Omron CX-Programmer project NuevoProyecto (CX-Programmer 9.50)

# PLC NewPLC1: CP1L-E EM

## Program P17_1_2 (cyclic task 0)
Local symbols
EV1 100.01 BOOL
EV2 100.02 BOOL
EV3 100.03 BOOL
Etapa_0 10.00 BOOL
Etapa_1 10.01 BOOL
Etapa_10 10.10 BOOL
Etapa_11 10.11 BOOL
Etapa_12 10.12 BOOL
Etapa_2 10.02 BOOL
Etapa_3 10.03 BOOL
Etapa_4 10.04 BOOL
Etapa_5 10.05 BOOL
Etapa_6 10.06 BOOL
Etapa_7 10.07 BOOL
Etapa_8 10.08 BOOL
Etapa_9 10.09 BOOL
F1 0.02 BOOL
FSF1 15.00 BOOL  ; Flanco Subida F1
MC 100.00 BOOL
S_1 0.01 BOOL
X 15.01 BOOL  ; Auxiliar X
Y 15.02 BOOL  ; Auxiliar Y
m 0.00 BOOL

### Section Sección1_Programa_principal
; Programa principal (Etapas 0 ... 23)

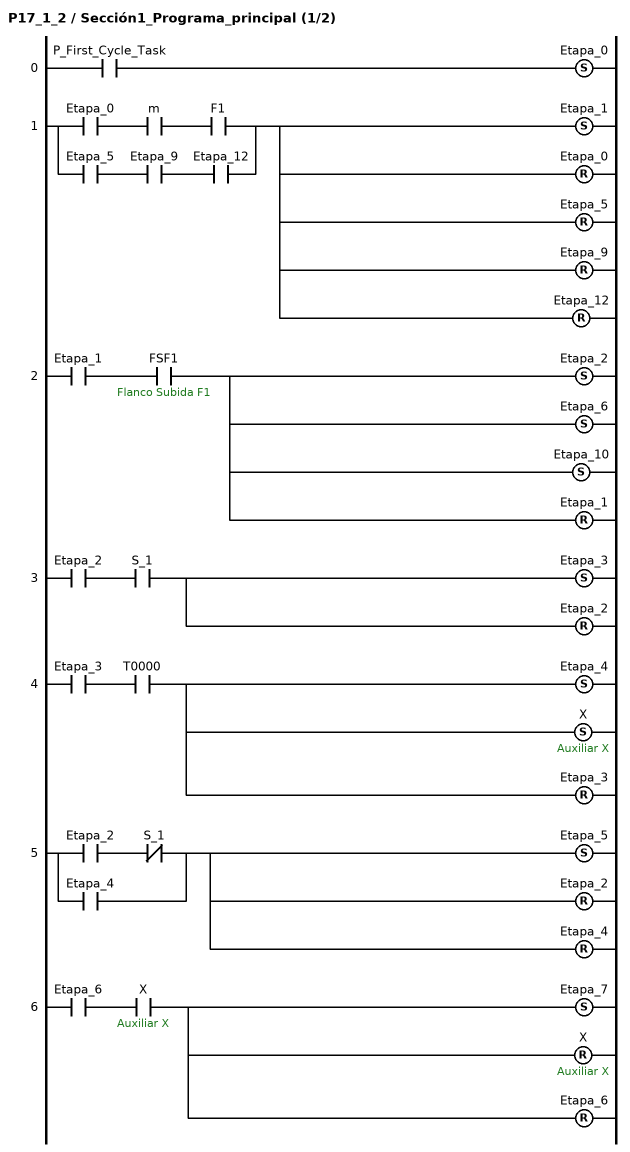
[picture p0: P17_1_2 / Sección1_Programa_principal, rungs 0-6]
; rung 0
LD P_First_Cycle_Task
SET Etapa_0
; rung 1
LD Etapa_0
AND m
AND F1
LD Etapa_5
AND Etapa_9
AND Etapa_12
ORLD
SET Etapa_1
RSET Etapa_0
RSET Etapa_5
RSET Etapa_9
RSET Etapa_12
; rung 2
LD Etapa_1
AND FSF1  ; Flanco Subida F1
SET Etapa_2
SET Etapa_6
SET Etapa_10
RSET Etapa_1
; rung 3
LD Etapa_2
AND S_1
SET Etapa_3
RSET Etapa_2
; rung 4
LD Etapa_3
AND T0000
SET Etapa_4
SET X  ; Auxiliar X
RSET Etapa_3
; rung 5
LD Etapa_2
ANDNOT S_1
OR Etapa_4
SET Etapa_5
RSET Etapa_2
RSET Etapa_4
; rung 6
LD Etapa_6
AND X  ; Auxiliar X
SET Etapa_7
RSET X  ; Auxiliar X
RSET Etapa_6

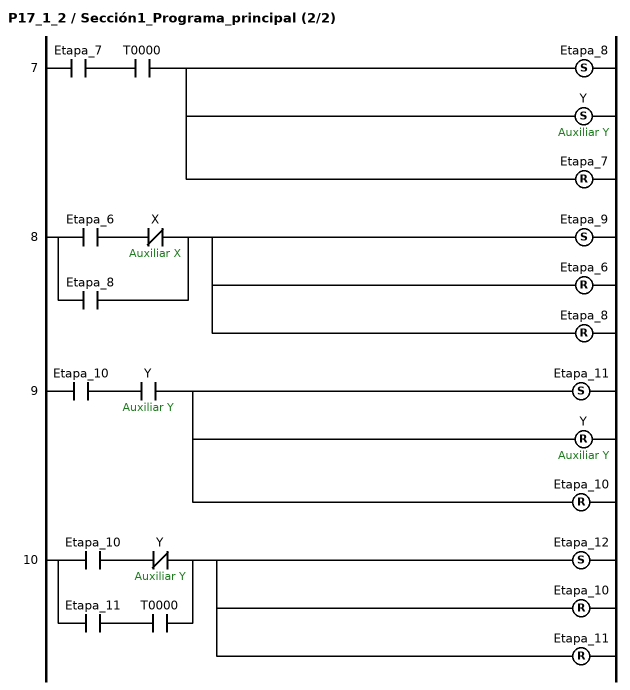
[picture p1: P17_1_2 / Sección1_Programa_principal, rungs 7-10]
; rung 7
LD Etapa_7
AND T0000
SET Etapa_8
SET Y  ; Auxiliar Y
RSET Etapa_7
; rung 8
LD Etapa_6
ANDNOT X  ; Auxiliar X
OR Etapa_8
SET Etapa_9
RSET Etapa_6
RSET Etapa_8
; rung 9
LD Etapa_10
AND Y  ; Auxiliar Y
SET Etapa_11
RSET Y  ; Auxiliar Y
RSET Etapa_10
; rung 10
LD Etapa_10
ANDNOT Y  ; Auxiliar Y
LD Etapa_11
AND T0000
ORLD
SET Etapa_12
RSET Etapa_10
RSET Etapa_11

### Section Sección2_Temporizador

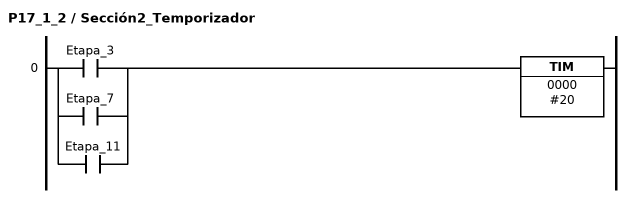
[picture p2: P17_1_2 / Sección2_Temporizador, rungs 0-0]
; rung 0
LD Etapa_3
OR Etapa_7
OR Etapa_11
TIM 0000 #20

### Section Sección3_FSF1

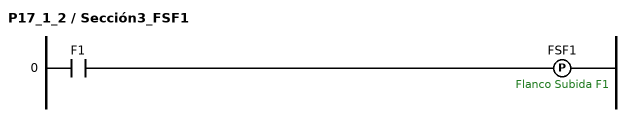
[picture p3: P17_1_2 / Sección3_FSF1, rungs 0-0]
; rung 0
LD F1
DIFU(013) FSF1  ; Flanco Subida F1

### Section Sección4_Salidas

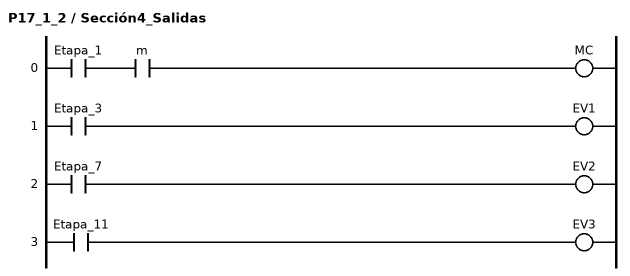
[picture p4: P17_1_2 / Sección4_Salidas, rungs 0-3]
; rung 0
LD Etapa_1
AND m
OUT MC
; rung 1
LD Etapa_3
OUT EV1
; rung 2
LD Etapa_7
OUT EV2
; rung 3
LD Etapa_11
OUT EV3

### Section Sección5_END
; rung 0: Fin de programa
END(001)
